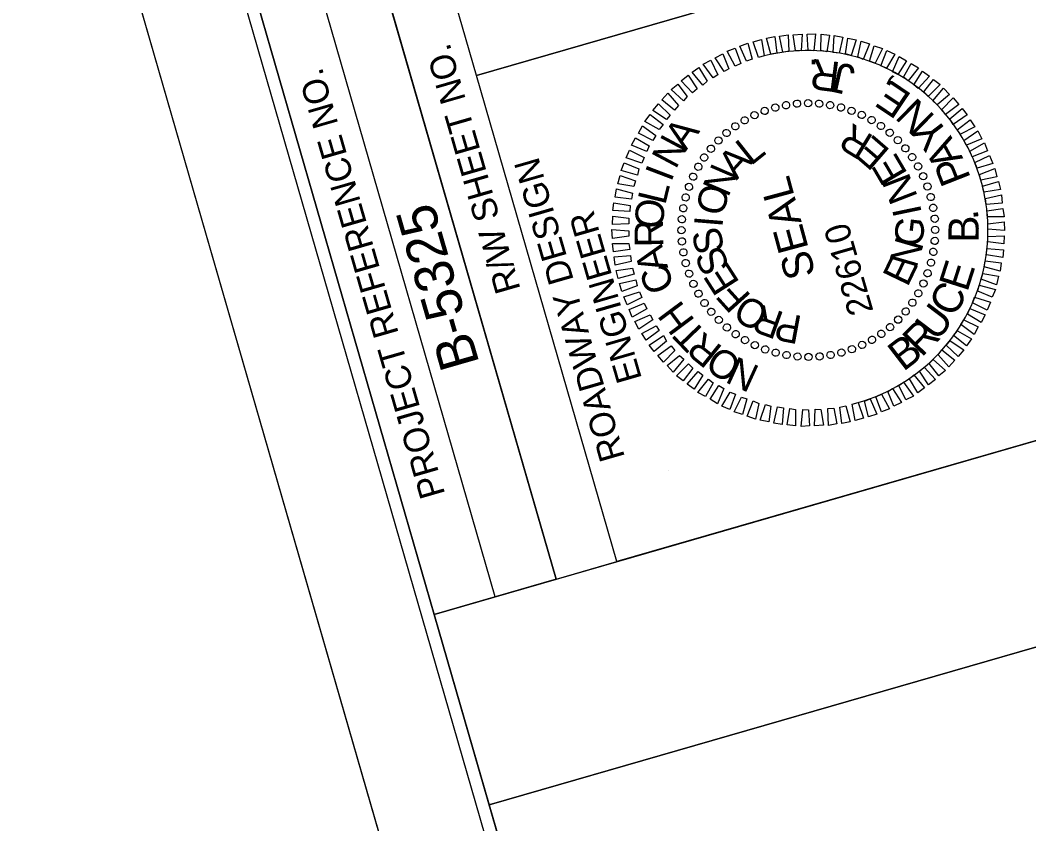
# Model space of a CAD drawing. Extents: x 2167139 to 2168658, y 842502 to 844423.
# Drawn here: x 2167138.9 to 2167338.2, y 843875.7 to 844034.6 of the extents above; entities that cross this region are included whole.
import ezdxf

# ---------------------------------------------------------------- set-up
doc = ezdxf.new("R2010")
doc.units = 0
for name, color, linetype in [('Old_Level_2', 7, 'Continuous'), ('Scratch_Level_0', 7, 'Continuous'), ('Sheet Clip Boundary CELL', 7, 'Continuous'), ('Sheet Cutting Line CELL', 7, 'Continuous'), ('Sheet Data Field CELL', 7, 'Continuous'), ('Sheet Layout Plan Border', 7, 'Continuous'), ('Sheet PE Seal CELL', 7, 'Continuous'), ('Sheet Plan CELL', 7, 'Continuous'), ('Sheet Plan Layout CELL', 7, 'Continuous'), ('Sheet Plot Border Inside CELL', 7, 'Continuous'), ('Sheet Plot Border Outside CELL', 7, 'Continuous')]:
    doc.layers.add(name, color=color, linetype=linetype)

msp = doc.modelspace()

# ---------------------------------------------------------------- linework, layer by layer
at = {"layer": 'Scratch_Level_0'}
msp.add_arc((2167294.67, 843993.08), 35.5, 286.1042, 106.1042, dxfattribs=at)
at = {"layer": 'Sheet Clip Boundary CELL'}
msp.add_lwpolyline([(2168333.42, 842899.61), (2168359.34, 842906.72), (2168266.95, 843188.11), (2168382.06, 843220.66), (2168502.28, 843263.66), (2168187.91, 844352.53), (2167382.3, 844119.94), (2167434.8, 843938.11), (2167231.61, 843879.44), (2167577.57, 842681.16)], close=True, dxfattribs=at)
at = {"layer": 'Sheet Cutting Line CELL'}
msp.add_line((2167138.92, 844119.41), (2167605.9, 842501.98), dxfattribs=at)
at = {"layer": 'Sheet Layout Plan Border'}
msp.add_lwpolyline([(2168586.35, 842975.21), (2168177.55, 844388.42), (2167371.94, 844155.82), (2167434.8, 843938.11), (2167231.61, 843879.44), (2167577.55, 842683.96)], close=True, dxfattribs=at)
at = {"layer": 'Sheet PE Seal CELL'}
for p, q in [((2167288.14, 844017.32), (2167288.14, 844017.32)), ((2167290.3, 844017.78), (2167290.3, 844017.78)), ((2167292.46, 844018.04), (2167292.46, 844018.04)), ((2167294.6, 844018.19), (2167294.6, 844018.19)), ((2167296.81, 844018.1), (2167296.81, 844018.1)), ((2167298.98, 844017.79), (2167298.98, 844017.79)), ((2167301.13, 844017.37), (2167301.13, 844017.37)), ((2167303.21, 844016.67), (2167303.21, 844016.67)), ((2167282.06, 844014.78), (2167282.06, 844014.78)), ((2167284.06, 844015.77), (2167284.06, 844015.77)), ((2167286.04, 844016.66), (2167286.04, 844016.66)), ((2167305.27, 844015.86), (2167305.27, 844015.86)), ((2167307.17, 844014.85), (2167307.17, 844014.85)), ((2167280.2, 844013.62), (2167280.2, 844013.62)), ((2167309.07, 844013.68), (2167309.07, 844013.68)), ((2167276.91, 844010.79), (2167276.91, 844010.79)), ((2167278.5, 844012.3), (2167278.5, 844012.3)), ((2167310.76, 844012.34), (2167310.76, 844012.34)), ((2167312.39, 844010.84), (2167312.39, 844010.84)), ((2167275.4, 844009.16), (2167275.4, 844009.16)), ((2167313.89, 844009.24), (2167313.89, 844009.24)), ((2167274.07, 844007.48), (2167274.07, 844007.48)), ((2167315.21, 844007.54), (2167315.21, 844007.54)), ((2167272.9, 844005.58), (2167272.9, 844005.58)), ((2167316.37, 844005.69), (2167316.37, 844005.69)), ((2167271.89, 844003.67), (2167271.89, 844003.67)), ((2167317.37, 844003.69), (2167317.37, 844003.69)), ((2167271.08, 844001.62), (2167271.08, 844001.62)), ((2167318.25, 844001.71), (2167318.25, 844001.71)), ((2167270.37, 843999.54), (2167270.37, 843999.54)), ((2167318.91, 843999.61), (2167318.91, 843999.61)), ((2167269.95, 843997.39), (2167269.95, 843997.39)), ((2167319.38, 843997.45), (2167319.38, 843997.45)), ((2167269.64, 843995.22), (2167269.64, 843995.22)), ((2167319.64, 843995.29), (2167319.64, 843995.29)), ((2167269.55, 843993.01), (2167269.55, 843993.01)), ((2167294.67, 843993.08), (2167294.67, 843993.08)), ((2167319.79, 843993.15), (2167319.79, 843993.15)), ((2167269.7, 843990.86), (2167269.7, 843990.86)), ((2167319.7, 843990.93), (2167319.7, 843990.93)), ((2167319.39, 843988.76), (2167319.39, 843988.76)), ((2167269.96, 843988.7), (2167269.96, 843988.7)), ((2167270.43, 843986.55), (2167270.43, 843986.55)), ((2167318.97, 843986.61), (2167318.97, 843986.61)), ((2167271.09, 843984.45), (2167271.09, 843984.45)), ((2167318.26, 843984.54), (2167318.26, 843984.54)), ((2167271.97, 843982.46), (2167271.97, 843982.46)), ((2167317.45, 843982.48), (2167317.45, 843982.48)), ((2167272.97, 843980.46), (2167272.97, 843980.46)), ((2167316.44, 843980.57), (2167316.44, 843980.57)), ((2167274.13, 843978.61), (2167274.13, 843978.61)), ((2167275.45, 843976.91), (2167275.45, 843976.91)), ((2167313.94, 843976.99), (2167313.94, 843976.99)), ((2167315.27, 843978.68), (2167315.27, 843978.68)), ((2167276.95, 843975.31), (2167276.95, 843975.31)), ((2167312.43, 843975.36), (2167312.43, 843975.36)), ((2167278.58, 843973.81), (2167278.58, 843973.81)), ((2167310.84, 843973.86), (2167310.84, 843973.86)), ((2167280.27, 843972.47), (2167280.27, 843972.47)), ((2167282.17, 843971.3), (2167282.17, 843971.3)), ((2167307.28, 843971.37), (2167307.28, 843971.37)), ((2167309.14, 843972.53), (2167309.14, 843972.53)), ((2167284.07, 843970.29), (2167284.07, 843970.29)), ((2167286.13, 843969.48), (2167286.13, 843969.48)), ((2167301.2, 843968.84), (2167301.2, 843968.84)), ((2167303.3, 843969.49), (2167303.3, 843969.49)), ((2167305.28, 843970.38), (2167305.28, 843970.38)), ((2167288.21, 843968.78), (2167288.21, 843968.78)), ((2167290.36, 843968.36), (2167290.36, 843968.36)), ((2167292.53, 843968.05), (2167292.53, 843968.05)), ((2167294.74, 843967.96), (2167294.74, 843967.96)), ((2167296.88, 843968.11), (2167296.88, 843968.11)), ((2167299.04, 843968.37), (2167299.04, 843968.37)), ((2167267.1, 843945.46), (2167267.1, 843945.46))]:
    msp.add_line(p, q, dxfattribs=at)
for points in [[(2167284.82, 844027.18), (2167283.78, 844030.26), (2167285.41, 844030.74), (2167285.98, 844027.52)], [(2167287.24, 844027.83), (2167286.43, 844030.98), (2167288.05, 844031.34), (2167288.42, 844028.07)], [(2167289.61, 844028.25), (2167289.01, 844031.41), (2167290.7, 844031.69), (2167290.84, 844028.35)], [(2167292.17, 844028.58), (2167291.7, 844031.67), (2167293.43, 844031.8), (2167293.29, 844028.48)], [(2167294.66, 844028.62), (2167294.43, 844031.78), (2167296.11, 844031.9), (2167295.78, 844028.53)], [(2167297.17, 844028.56), (2167297.18, 844031.79), (2167298.85, 844031.6), (2167298.34, 844028.33)], [(2167299.57, 844028.21), (2167299.81, 844031.51), (2167301.51, 844031.22), (2167300.76, 844028.04)], [(2167302.05, 844027.89), (2167302.46, 844030.98), (2167304.16, 844030.68), (2167303.13, 844027.58)], [(2167280.21, 844025.49), (2167278.64, 844028.42), (2167280.23, 844029.03), (2167281.31, 844026.01)], [(2167282.43, 844026.44), (2167281.15, 844029.45), (2167282.75, 844030.02), (2167283.56, 844026.87)], [(2167304.45, 844027.33), (2167305.12, 844030.44), (2167306.74, 844029.87), (2167305.54, 844026.81)], [(2167306.79, 844026.45), (2167307.67, 844029.51), (2167309.33, 844029), (2167307.88, 844026.09)], [(2167275.89, 844023.15), (2167273.9, 844025.9), (2167275.4, 844026.65), (2167276.8, 844023.77)], [(2167278.03, 844024.39), (2167276.24, 844027.15), (2167277.79, 844027.91), (2167278.96, 844024.97)], [(2167309.03, 844025.53), (2167310.18, 844028.57), (2167311.74, 844027.88), (2167310.09, 844025.11)], [(2167311.34, 844024.38), (2167312.6, 844027.4), (2167314.06, 844026.52), (2167312.33, 844023.83)], [(2167273.81, 844021.71), (2167271.71, 844024.28), (2167273.05, 844025.24), (2167274.68, 844022.48)], [(2167313.48, 844023.28), (2167314.98, 844026), (2167316.47, 844025.18), (2167314.42, 844022.56)], [(2167271.8, 844020.2), (2167269.54, 844022.61), (2167270.9, 844023.68), (2167272.72, 844020.98)], [(2167315.52, 844021.79), (2167317.23, 844024.52), (2167318.62, 844023.51), (2167316.41, 844021.06)], [(2167317.49, 844020.38), (2167319.43, 844022.86), (2167320.7, 844021.88), (2167318.37, 844019.49)], [(2167270.01, 844018.64), (2167267.55, 844020.84), (2167268.86, 844021.9), (2167270.76, 844019.48)], [(2167319.3, 844018.61), (2167321.38, 844021.14), (2167322.58, 844019.87), (2167320.14, 844017.86)], [(2167268.26, 844016.78), (2167265.7, 844018.8), (2167266.88, 844020.13), (2167269.03, 844017.73)], [(2167321.05, 844016.88), (2167323.3, 844019.19), (2167324.4, 844017.9), (2167321.79, 844015.95)], [(2167266.65, 844014.96), (2167263.95, 844016.73), (2167265.08, 844018.05), (2167267.4, 844015.8)], [(2167322.67, 844015.06), (2167325.1, 844017.11), (2167326.09, 844015.83), (2167323.31, 844013.94)], [(2167265.19, 844012.98), (2167262.39, 844014.57), (2167263.4, 844015.95), (2167265.96, 844013.93)], [(2167324.12, 844012.92), (2167326.68, 844014.86), (2167327.55, 844013.5), (2167324.75, 844012.01)], [(2167263.95, 844010.8), (2167261.09, 844012.21), (2167261.91, 844013.7), (2167264.51, 844011.74)], [(2167262.77, 844008.59), (2167259.7, 844009.83), (2167260.52, 844011.32), (2167263.22, 844009.71)], [(2167325.41, 844010.8), (2167328.15, 844012.68), (2167328.95, 844011.14), (2167325.94, 844009.86)], [(2167261.8, 844006.33), (2167258.65, 844007.34), (2167259.34, 844008.9), (2167262.21, 844007.44)], [(2167326.6, 844008.65), (2167329.46, 844010.3), (2167330.06, 844008.76), (2167327.08, 844007.53)], [(2167327.56, 844006.42), (2167330.48, 844007.84), (2167331.14, 844006.26), (2167328.04, 844005.31)], [(2167260.93, 844003.94), (2167257.66, 844004.82), (2167258.31, 844006.36), (2167261.2, 844005.17)], [(2167328.49, 844004.09), (2167331.55, 844005.23), (2167331.95, 844003.63), (2167328.78, 844002.92)], [(2167260.18, 844001.7), (2167257.06, 844002.2), (2167257.46, 844003.88), (2167260.49, 844002.78)], [(2167259.71, 843999.17), (2167256.53, 843999.55), (2167256.77, 844001.23), (2167259.93, 844000.38)], [(2167329.11, 844001.77), (2167332.23, 844002.67), (2167332.64, 844001.07), (2167329.39, 844000.6)], [(2167329.66, 843999.33), (2167332.84, 844000.04), (2167333.01, 843998.37), (2167329.8, 843998.12)], [(2167259.42, 843996.74), (2167256.07, 843996.97), (2167256.26, 843998.48), (2167259.44, 843997.94)], [(2167329.94, 843996.91), (2167333.14, 843997.37), (2167333.36, 843995.71), (2167330.13, 843995.72)], [(2167259.18, 843994.33), (2167255.99, 843994.19), (2167256.04, 843995.82), (2167259.22, 843995.44)], [(2167259.22, 843991.84), (2167255.96, 843991.42), (2167255.87, 843993.17), (2167259.17, 843992.92)], [(2167330.12, 843994.31), (2167333.38, 843994.73), (2167333.47, 843992.98), (2167330.17, 843993.23)], [(2167330.16, 843991.82), (2167333.35, 843991.96), (2167333.3, 843990.33), (2167330.12, 843990.72)], [(2167259.4, 843989.24), (2167256.2, 843988.79), (2167255.98, 843990.44), (2167259.21, 843990.44)], [(2167329.92, 843989.41), (2167333.27, 843989.18), (2167333.08, 843987.67), (2167329.9, 843988.21)], [(2167259.68, 843986.83), (2167256.5, 843986.12), (2167256.33, 843987.78), (2167259.54, 843988.03)], [(2167329.63, 843986.98), (2167332.81, 843986.6), (2167332.57, 843984.92), (2167329.41, 843985.78)], [(2167260.23, 843984.38), (2167257.11, 843983.48), (2167256.7, 843985.08), (2167259.95, 843985.55)], [(2167260.85, 843982.06), (2167257.79, 843980.92), (2167257.39, 843982.52), (2167260.56, 843983.23)], [(2167329.16, 843984.46), (2167332.28, 843983.95), (2167331.88, 843982.27), (2167328.85, 843983.38)], [(2167261.78, 843979.73), (2167258.86, 843978.31), (2167258.2, 843979.89), (2167261.3, 843980.84)], [(2167328.41, 843982.21), (2167331.68, 843981.33), (2167331.03, 843979.79), (2167328.14, 843980.99)], [(2167327.54, 843979.82), (2167330.69, 843978.81), (2167330, 843977.25), (2167327.13, 843978.72)], [(2167262.74, 843977.51), (2167259.88, 843975.85), (2167259.28, 843977.39), (2167262.26, 843978.62)], [(2167326.57, 843977.57), (2167329.64, 843976.32), (2167328.82, 843974.83), (2167326.12, 843976.45)], [(2167263.93, 843975.35), (2167261.19, 843973.47), (2167260.39, 843975.01), (2167263.4, 843976.29)], [(2167325.39, 843975.35), (2167328.25, 843973.94), (2167327.43, 843972.45), (2167324.83, 843974.41)], [(2167265.22, 843973.23), (2167262.66, 843971.29), (2167261.79, 843972.66), (2167264.59, 843974.14)], [(2167324.15, 843973.17), (2167326.95, 843971.59), (2167325.94, 843970.2), (2167323.38, 843972.22)], [(2167266.67, 843971.1), (2167264.24, 843969.04), (2167263.25, 843970.32), (2167266.03, 843972.21)], [(2167322.69, 843971.19), (2167325.39, 843969.42), (2167324.26, 843968.1), (2167321.94, 843970.35)], [(2167268.29, 843969.27), (2167266.04, 843966.96), (2167264.94, 843968.26), (2167267.55, 843970.21)], [(2167321.08, 843969.37), (2167323.64, 843967.35), (2167322.46, 843966.02), (2167320.32, 843968.42)], [(2167270.04, 843967.54), (2167267.96, 843965.01), (2167266.76, 843966.28), (2167269.2, 843968.29)], [(2167319.33, 843967.51), (2167321.79, 843965.31), (2167320.48, 843964.25), (2167318.58, 843966.67)], [(2167271.85, 843965.77), (2167269.91, 843963.29), (2167268.64, 843964.27), (2167270.97, 843966.66)], [(2167273.82, 843964.36), (2167272.11, 843961.63), (2167270.72, 843962.64), (2167272.93, 843965.1)], [(2167317.54, 843965.96), (2167319.8, 843963.54), (2167318.44, 843962.47), (2167316.62, 843965.17)], [(2167275.86, 843962.87), (2167274.36, 843960.15), (2167272.87, 843960.97), (2167274.92, 843963.59)], [(2167313.45, 843963), (2167315.44, 843960.25), (2167313.94, 843959.5), (2167312.54, 843962.38)], [(2167315.53, 843964.44), (2167317.63, 843961.87), (2167316.29, 843960.91), (2167314.66, 843963.67)], [(2167278, 843961.77), (2167276.74, 843958.75), (2167275.28, 843959.64), (2167277.01, 843962.32)], [(2167280.31, 843960.62), (2167279.16, 843957.58), (2167277.6, 843958.28), (2167279.25, 843961.04)], [(2167311.31, 843961.76), (2167313.1, 843959), (2167311.55, 843958.24), (2167310.38, 843961.18)], [(2167282.55, 843959.71), (2167281.67, 843956.64), (2167280.01, 843957.15), (2167281.46, 843960.07)], [(2167284.89, 843958.82), (2167284.22, 843955.71), (2167282.6, 843956.28), (2167283.8, 843959.34)], [(2167304.52, 843958.97), (2167305.56, 843955.89), (2167303.93, 843955.42), (2167303.36, 843958.64)], [(2167306.91, 843959.71), (2167308.19, 843956.7), (2167306.59, 843956.13), (2167305.78, 843959.28)], [(2167309.13, 843960.66), (2167310.7, 843957.74), (2167309.11, 843957.12), (2167308.03, 843960.14)], [(2167287.29, 843958.26), (2167286.88, 843955.18), (2167285.18, 843955.47), (2167286.21, 843958.58)], [(2167289.77, 843957.94), (2167289.53, 843954.64), (2167287.83, 843954.93), (2167288.58, 843958.11)], [(2167292.17, 843957.59), (2167292.16, 843954.36), (2167290.49, 843954.56), (2167291, 843957.83)], [(2167294.68, 843957.53), (2167294.91, 843954.38), (2167293.23, 843954.25), (2167293.56, 843957.63)], [(2167297.17, 843957.58), (2167297.64, 843954.49), (2167295.91, 843954.35), (2167296.05, 843957.67)], [(2167299.73, 843957.9), (2167300.33, 843954.74), (2167298.64, 843954.46), (2167298.5, 843957.81)], [(2167302.1, 843958.32), (2167302.91, 843955.17), (2167301.29, 843954.81), (2167300.92, 843958.09)]]:
    msp.add_lwpolyline(points, close=True, dxfattribs=at)
for centre, major_axis in [((2167292.44, 844018.06), (-0.064, 0.717)), ((2167294.62, 844018.16), (-0.001, 0.72)), ((2167296.81, 844018.06), (0.061, 0.717)), ((2167286.05, 844016.63), (-0.247, 0.676)), ((2167288.13, 844017.29), (-0.188, 0.695)), ((2167290.27, 844017.77), (-0.126, 0.709)), ((2167298.98, 844017.78), (0.124, 0.709)), ((2167301.12, 844017.31), (0.185, 0.696)), ((2167303.21, 844016.66), (0.245, 0.677)), ((2167282.09, 844014.77), (-0.361, 0.623)), ((2167284.03, 844015.79), (-0.305, 0.652)), ((2167305.23, 844015.83), (0.303, 0.653)), ((2167307.17, 844014.82), (0.359, 0.624)), ((2167278.51, 844012.26), (-0.464, 0.551)), ((2167280.25, 844013.59), (-0.414, 0.589)), ((2167309.02, 844013.65), (0.412, 0.591)), ((2167310.76, 844012.32), (0.462, 0.552)), ((2167276.9, 844010.78), (-0.51, 0.508)), ((2167312.37, 844010.84), (0.508, 0.51)), ((2167275.43, 844009.16), (-0.552, 0.462)), ((2167313.85, 844009.23), (0.551, 0.464)), ((2167274.1, 844007.42), (-0.591, 0.412)), ((2167315.19, 844007.5), (0.589, 0.414)), ((2167272.93, 844005.58), (-0.624, 0.359)), ((2167316.37, 844005.66), (0.623, 0.361)), ((2167271.92, 844003.63), (-0.653, 0.303)), ((2167317.38, 844003.72), (0.652, 0.305)), ((2167271.09, 844001.61), (-0.677, 0.245)), ((2167318.22, 844001.7), (0.676, 0.247)), ((2167270.43, 843999.52), (-0.696, 0.185)), ((2167318.88, 843999.61), (0.695, 0.188)), ((2167269.96, 843997.39), (-0.709, 0.124)), ((2167319.36, 843997.48), (0.709, 0.126)), ((2167269.68, 843995.22), (-0.717, 0.061)), ((2167319.65, 843995.31), (0.717, 0.064)), ((2167269.59, 843993.03), (-0.72, -0.001)), ((2167319.75, 843993.12), (0.72, 0.001)), ((2167269.69, 843990.84), (-0.717, -0.064)), ((2167319.66, 843990.94), (0.717, -0.061)), ((2167269.98, 843988.68), (-0.709, -0.126)), ((2167319.38, 843988.77), (0.709, -0.124)), ((2167270.46, 843986.54), (-0.695, -0.188)), ((2167318.91, 843986.63), (0.696, -0.185)), ((2167271.12, 843984.46), (-0.676, -0.247)), ((2167318.25, 843984.54), (0.677, -0.245)), ((2167271.96, 843982.44), (-0.652, -0.305)), ((2167317.42, 843982.52), (0.653, -0.303)), ((2167272.97, 843980.5), (-0.623, -0.361)), ((2167316.41, 843980.58), (0.624, -0.359)), ((2167274.15, 843978.65), (-0.589, -0.414)), ((2167315.24, 843978.73), (0.591, -0.412)), ((2167275.49, 843976.92), (-0.551, -0.464)), ((2167313.91, 843976.99), (0.552, -0.462)), ((2167276.97, 843975.31), (-0.508, -0.51)), ((2167312.44, 843975.37), (0.51, -0.508)), ((2167278.58, 843973.83), (-0.462, -0.552)), ((2167280.32, 843972.51), (-0.412, -0.591)), ((2167309.09, 843972.56), (0.414, -0.589)), ((2167310.83, 843973.89), (0.464, -0.551)), ((2167282.17, 843971.33), (-0.359, -0.624)), ((2167284.11, 843970.33), (-0.303, -0.653)), ((2167305.31, 843970.37), (0.305, -0.652)), ((2167307.25, 843971.38), (0.361, -0.623)), ((2167286.14, 843969.49), (-0.245, -0.677)), ((2167288.22, 843968.84), (-0.185, -0.696)), ((2167290.36, 843968.37), (-0.124, -0.709)), ((2167292.53, 843968.09), (-0.061, -0.717)), ((2167296.9, 843968.1), (0.064, -0.717)), ((2167299.07, 843968.39), (0.126, -0.709)), ((2167301.21, 843968.86), (0.188, -0.695)), ((2167303.29, 843969.52), (0.247, -0.676)), ((2167294.72, 843968), (0.001, -0.72))]:
    msp.add_ellipse(centre, major_axis=major_axis, ratio=0.999708, dxfattribs=at)
at = {"layer": 'Sheet Plan CELL'}
for p, q in [((2167244.82, 843924.07), (2167189.31, 844116.25)), ((2167244.82, 843924.07), (2167189.31, 844116.25)), ((2167232.78, 843920.58), (2167177.3, 844112.79)), ((2167229.07, 844023.66), (2167337.11, 844054.87)), ((2167244.82, 843924.07), (2167256.82, 843927.54))]:
    msp.add_line(p, q, dxfattribs=at)
for points in [[(2167165.23, 844109.34), (2167581.32, 842668.17), (2168590.12, 842959.42), (2168174.04, 844400.57)], [(2168590.12, 842959.42), (2167581.35, 842668.15), (2167220.72, 843917.11), (2167364.89, 843958.75), (2167309.41, 844150.94), (2168174.04, 844400.57)], [(2167229.07, 844023.66), (2167201.32, 844119.72), (2167309.41, 844150.94), (2167337.16, 844054.87)], [(2167220.72, 843917.11), (2167165.23, 844109.34), (2167189.31, 844116.25), (2167244.82, 843924.07)], [(2167256.82, 843927.54), (2167229.07, 844023.66), (2167337.16, 844054.87), (2167364.89, 843958.75)]]:
    msp.add_lwpolyline(points, close=True, dxfattribs=at)
at = {"layer": 'Sheet Plan Layout CELL'}
for points in [[(2167581.35, 842668.15), (2168590.12, 842959.42), (2168174.04, 844400.56), (2167368.43, 844167.97), (2167434.8, 843938.11), (2167231.61, 843879.44)], [(2167434.8, 843938.11), (2167368.43, 844167.99), (2167165.23, 844109.35), (2167231.61, 843879.44)]]:
    msp.add_lwpolyline(points, close=True, dxfattribs=at)
at = {"layer": 'Sheet Plot Border Inside CELL'}
msp.add_lwpolyline([(2168635.11, 842812.65), (2168172.98, 844413.26), (2167159.38, 844120.64), (2167621.51, 842520.01)], close=True, dxfattribs=at)
at = {"layer": 'Sheet Plot Border Outside CELL'}
msp.add_lwpolyline([(2168657.93, 842805.71), (2168190.95, 844423.15), (2167138.92, 844119.41), (2167605.9, 842501.98)], close=True, dxfattribs=at)

# ---------------------------------------------------------------- texts
at = {"layer": 'Old_Level_2'}
for s, rotation, p in [('.', 180.1958, (2167296.82, 844026.78)), ('R', 172.7156, (2167301.19, 844026.22)), ('J', 167.4578, (2167304.2, 844025.48)), (',', 153.2236, (2167311.87, 844022.14)), ('E', 146.1143, (2167315.34, 844019.79)), ('N', 135.3885, (2167319.95, 844015.48)), ('Y', 127.4754, (2167322.79, 844011.78)), ('A', 118.6351, (2167325.33, 844007.24)), ('P', 111.5258, (2167326.85, 844003.34)), ('B', 89.595, (2167328.35, 843990.57)), ('.', 97.2917, (2167328.39, 843995.11)), ('E', 72.2853, (2167326.08, 843980.67)), ('C', 62.7032, (2167323.58, 843975.61)), ('U', 52.7656, (2167320.13, 843970.88)), ('R', 45.2853, (2167317.03, 843967.76)), ('B', 37.5887, (2167313.43, 843964.99))]:
    msp.add_text(s, height=6, rotation=rotation, dxfattribs=at).set_placement(p)
at = {"layer": 'Sheet Data Field CELL'}
msp.add_text('B-5325', height=7.75, rotation=106.1042, dxfattribs=at).set_placement((2167229.73, 843966.75))
at = {"layer": 'Sheet PE Seal CELL'}
for s, height, rotation, p in [('A', 5.64, 54.7214, (2167270.47, 844008.57)), ('R', 5.64, 148.5856, (2167307.81, 844011.55)), ('N', 5.64, 61.9231, (2167268.46, 844004.92)), ('L', 5.64, 38.5051, (2167283.28, 844005.66)), ('E', 5.64, 139.2283, (2167311.05, 844008.79)), ('A', 5.64, 47.8645, (2167280.51, 844002.83)), ('E', 5.64, 120.516, (2167314.4, 844004.24)), ('I', 5.64, 69.1243, (2167267.56, 844002.42)), ('N', 5.64, 66.5808, (2167278.8, 843999.37)), ('SEAL', 5.998, 105.1042, (2167296.16, 843984.3)), ('N', 5.64, 111.1606, (2167316.35, 843999.65)), ('L', 5.64, 76.3251, (2167266.38, 843997.87)), ('O', 5.64, 75.9377, (2167277.81, 843995.6)), ('O', 5.64, 83.5254, (2167265.82, 843993.13)), ('I', 5.64, 101.8054, (2167317.13, 843996.39)), ('R', 5.64, 90.7253, (2167266.03, 843989.7)), ('I', 5.64, 85.2938, (2167277.69, 843993.48)), ('G', 5.64, 83.0944, (2167317.12, 843989.57)), ('S', 5.64, 104.0046, (2167278.21, 843989.16)), ('   22610  ', 4.975, 106.1042, (2167309.11, 843971.74)), ('N', 5.64, 73.7382, (2167316.02, 843985.29)), ('A', 5.64, 105.1245, (2167267.01, 843985.61)), ('S', 5.64, 113.3598, (2167279.26, 843985.71)), ('E', 5.64, 64.3811, (2167314.26, 843981.66)), ('C', 5.64, 112.3241, (2167268.39, 843981.9)), ('E', 5.64, 122.7153, (2167281.22, 843982.69)), ('F', 5.64, 132.0712, (2167283.55, 843980.03)), ('H', 5.64, 126.7237, (2167272.42, 843975.15)), ('O', 5.64, 150.7854, (2167287.3, 843977.68)), ('R', 5.64, 160.1439, (2167290.14, 843976.68)), ('P', 5.64, 169.5031, (2167293.66, 843976.03)), ('T', 5.64, 133.924, (2167274.91, 843972.49)), ('R', 5.64, 141.1247, (2167277.96, 843969.83)), ('O', 5.64, 148.3259, (2167281.9, 843967.37)), ('N', 5.64, 155.5277, (2167285.32, 843965.97))]:
    msp.add_text(s, height=height, rotation=rotation, dxfattribs=at).set_placement(p)
at = {"layer": 'Sheet Plan CELL'}
for s, height, p in [('R/W SHEET NO.', 5.0001, (2167237.84, 843981.39)), ('PROJECT REFERENCE NO.', 5.0001, (2167222.94, 843940.86)), ('ROADWAY DESIGN', 5.0001, (2167258.46, 843948.18)), ('ENGINEER', 5, (2167261.82, 843963.71))]:
    msp.add_text(s, height=height, rotation=106.1042, dxfattribs=at).set_placement(p)

doc.saveas('drawing.dxf')
